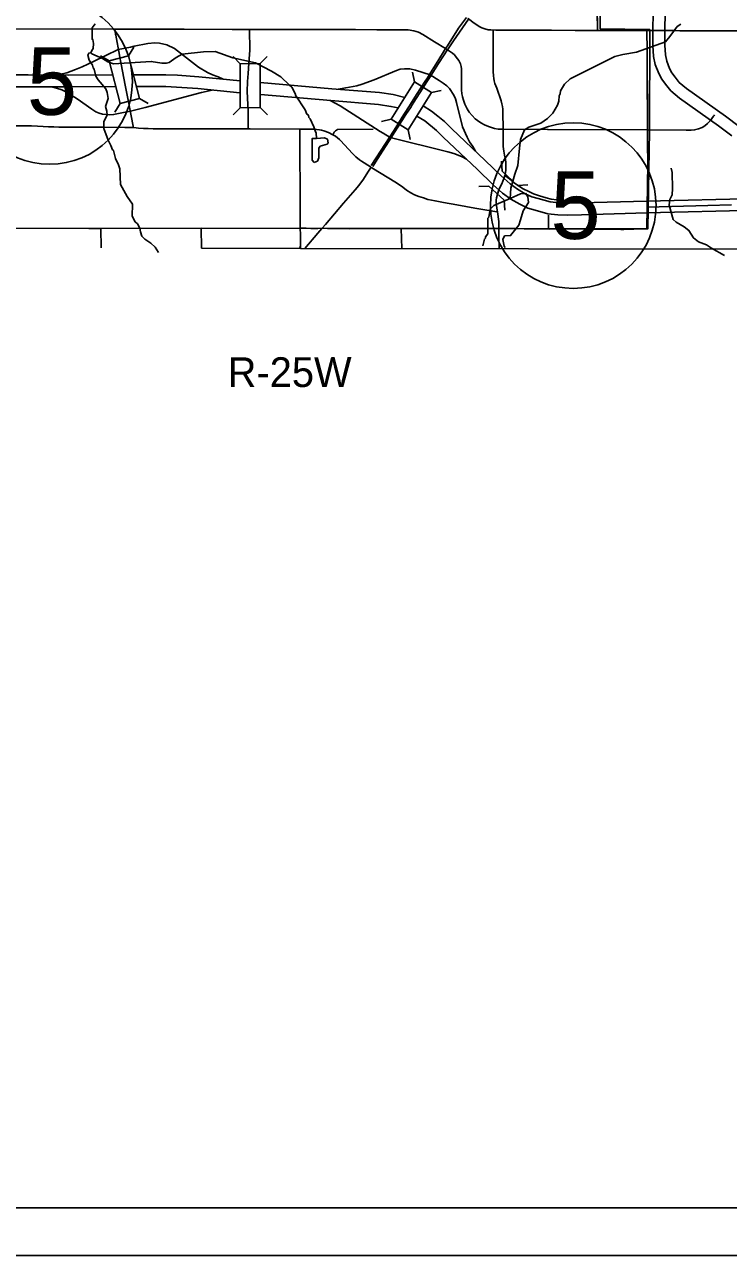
# Model space of a CAD drawing. Extents: x -1403959 to 81668, y -1400582 to 11018.
# Drawn here: x 6493 to 6836, y 7241 to 7841 of the extents above; entities that cross this region are included whole.
import ezdxf

# ---------------------------------------------------------------- set-up
doc = ezdxf.new("R2010")
doc.units = 0
for name, color, linetype in [('tdCiCityStreetTxt', 7, 'Continuous'), ('tdCiRRCL', 7, 'Continuous'), ('tdCiSectNmbr', 7, 'Continuous'), ('tdCiSectTwpRng', 7, 'Continuous'), ('tdCoCityStreetMajor', 7, 'Continuous'), ('tdCoCityStreetMinor', 7, 'Continuous'), ('tdCoClipBndry', 7, 'Continuous'), ('tdCoDivCarto', 7, 'Continuous'), ('tdCoIntCL', 7, 'Continuous'), ('tdCoSectLine', 7, 'Continuous'), ('tdCoStrucSecFHWANum', 7, 'Continuous'), ('tdCoSurfAsphalt', 7, 'Continuous'), ('tdCoSurfBitum', 7, 'Continuous'), ('tdCoSurfEarth', 7, 'Continuous')]:
    doc.layers.add(name, color=color, linetype=linetype)

msp = doc.modelspace()

# ---------------------------------------------------------------- linework, layer by layer
at = {"layer": 'tdCiCityStreetTxt'}
for p, q in [((6543.57, 7825.61), (6546.06, 7829.8)), ((6534.13, 7823.2), (6529.93, 7825.69)), ((6534.13, 7823.2), (6543.57, 7825.61)), ((6539.43, 7802.42), (6534.13, 7823.2)), ((6543.57, 7825.61), (6548.87, 7804.83)), ((6597.9, 7821.79), (6594.43, 7825.22)), ((6607.64, 7821.83), (6611.07, 7825.29)), ((6597.9, 7821.79), (6607.64, 7821.83)), ((6597.98, 7800.34), (6597.9, 7821.79)), ((6607.64, 7821.83), (6607.73, 7800.38)), ((6682.86, 7812.92), (6681.78, 7817.68)), ((6671.42, 7794.78), (6682.86, 7812.92)), ((6682.86, 7812.92), (6691.1, 7807.72)), ((6548.87, 7804.83), (6539.43, 7802.42)), ((6548.87, 7804.83), (6548.87, 7804.83)), ((6548.87, 7804.83), (6553.07, 7802.34)), ((6691.1, 7807.72), (6679.66, 7789.58)), ((6691.1, 7807.72), (6695.86, 7808.8)), ((6539.43, 7802.42), (6536.94, 7798.23)), ((6597.98, 7800.34), (6594.55, 7796.88)), ((6607.73, 7800.38), (6597.98, 7800.34)), ((6607.73, 7800.38), (6607.73, 7800.38)), ((6607.73, 7800.38), (6611.19, 7796.95)), ((6671.42, 7794.78), (6666.66, 7793.71)), ((6679.66, 7789.58), (6671.42, 7794.78)), ((6679.66, 7789.58), (6679.66, 7789.58)), ((6679.66, 7789.58), (6680.74, 7784.83))]:
    msp.add_line(p, q, dxfattribs=at)
at = {"layer": 'tdCiRRCL'}
for p, q in [((6579.15, 7731.96), (6627.37, 7731.86)), ((6627.37, 7731.86), (6997.83, 7731.15))]:
    msp.add_line(p, q, dxfattribs=at)
for points in [[(6627.37, 7731.86), (6627.23, 7738.5), (6627.19, 7741.7), (6723.95, 7741.45), (6748.03, 7741.41), (6748.63, 7741.41), (6795.97, 7741.34), (6796.1, 7751.99), (6796.35, 7773.39), (6796.26, 7789.53), (6796.11, 7824.8), (6796.13, 7828.12), (6796.01, 7837.97), (6794.48, 7837.97), (6792.7, 7837.97), (6783.45, 7837.92), (6776.54, 7837.95), (6771.85, 7837.99), (6771.78, 7850.5)], [(6771.78, 7850.5), (6771.85, 7837.99), (6776.54, 7837.95), (6783.45, 7837.92), (6792.7, 7837.97), (6794.48, 7837.97), (6796.01, 7837.97), (6796.13, 7828.12), (6796.11, 7824.8), (6796.26, 7789.53), (6796.35, 7773.39), (6796.1, 7751.99), (6825.69, 7752.71), (6837.1, 7752.99)], [(6387.68, 7731.88), (6387.75, 7734.68), (6387.88, 7736.33), (6388.19, 7738.91), (6388.51, 7740.78), (6388.71, 7741.72), (6433.9, 7741.75), (6433.91, 7756.87), (6439.59, 7756.88), (6446.88, 7752.02), (6457.28, 7751.94), (6457.24, 7741.46), (6578.95, 7741.63), (6579.15, 7731.96)], [(6837.1, 7752.99), (6825.69, 7752.71), (6796.1, 7751.99), (6795.97, 7741.34), (6748.63, 7741.41), (6748.03, 7741.41), (6723.95, 7741.45), (6627.19, 7741.7), (6627.23, 7738.5), (6627.37, 7731.86)]]:
    msp.add_lwpolyline(points, dxfattribs=at)
at = {"layer": 'tdCiSectNmbr'}
for points in [[(6708.11, 7844.34), (6704.28, 7839.09), (6698.85, 7830.41), (6697.97, 7829.14)], [(6698.84, 7828.58), (6701.73, 7832.94), (6709.07, 7843.55)], [(6708.72, 7843.9), (6709.11, 7843.61), (6711.92, 7841.54), (6714.6, 7839.79), (6715.67, 7839.26), (6717.02, 7838.72), (6718.7, 7838.36), (6719.91, 7838.25), (6722.47, 7838.19), (6726.78, 7838.11), (6734.64, 7838.13), (6749.45, 7838.05), (6761.01, 7838.02)], [(6726.04, 7789.88), (6725.9, 7798.22), (6725.83, 7799.63), (6725.66, 7800.88), (6725.38, 7802.2), (6724.94, 7803.69), (6722.82, 7809.8), (6721.99, 7812.11), (6721.61, 7813.51), (6721.39, 7814.62), (6721.23, 7815.8), (6721.12, 7817.94), (6721.11, 7829.83), (6721.14, 7838.22)], [(6761.01, 7838.02), (6762.83, 7838.02), (6762.92, 7838.02)], [(6762.92, 7838.02), (6765.9, 7837.99)], [(6765.9, 7837.99), (6766.31, 7837.99), (6771.85, 7837.99)], [(6771.85, 7837.99), (6779.66, 7837.94), (6783.45, 7837.97)], [(6783.45, 7837.97), (6787.41, 7838), (6789.83, 7838.02), (6792.7, 7838.01)], [(6792.7, 7838.01), (6794.48, 7838)], [(6794.48, 7838), (6796.01, 7838), (6796.01, 7838)], [(6796.01, 7838), (6801.6, 7837.98), (6801.97, 7837.98)], [(6801.97, 7837.98), (6802.38, 7837.98), (6804.53, 7837.95)], [(6804.53, 7837.95), (6810.13, 7837.88)], [(6810.13, 7837.88), (6811.93, 7837.86), (6815.83, 7837.84)], [(6815.83, 7837.84), (6826.23, 7837.78), (6834.06, 7837.73), (6863.52, 7837.73), (6894.38, 7837.56), (6907.58, 7837.64), (6907.8, 7837.64)], [(6697.97, 7829.14), (6697.41, 7828.3), (6694.66, 7823.77), (6690.66, 7817.42), (6689.09, 7814.92), (6688.07, 7813.33), (6683.86, 7806.72), (6680.92, 7802.14)], [(6688.84, 7812.94), (6688.84, 7812.94), (6690.45, 7815.43), (6694.5, 7821.87), (6697.21, 7826.08), (6698.37, 7827.9), (6698.69, 7828.37)], [(6698.69, 7828.37), (6698.84, 7828.58)], [(6698.84, 7828.58), (6701.26, 7826.88), (6702.22, 7826.13), (6703.17, 7824.97), (6704.38, 7823.35), (6705.15, 7821.65), (6705.47, 7820.47), (6705.68, 7819.31), (6705.73, 7817.9), (6705.73, 7815.02), (6705.62, 7811.15), (6705.68, 7809.09), (6705.91, 7807.07), (6706.11, 7805.77), (6706.13, 7805.7)], [(6543.88, 7801.67), (6541.99, 7811.39), (6539.95, 7821.58), (6539.14, 7825.73)], [(6681.71, 7801.8), (6682.51, 7803.04), (6686.53, 7809.37), (6688.84, 7812.94)], [(6706.13, 7805.7), (6706.59, 7803.99), (6707.27, 7802.16), (6707.95, 7800.78), (6708.45, 7799.83), (6709.46, 7798.18), (6710.82, 7796.51), (6712.34, 7794.9), (6713.49, 7794.08), (6715.08, 7792.96), (6716.91, 7791.97), (6718.82, 7791.14), (6721.84, 7790.25), (6723.48, 7789.98), (6725.14, 7789.86), (6726.04, 7789.83)], [(6545.96, 7790.67), (6545.86, 7791.32), (6544.09, 7800.68), (6543.88, 7801.67)], [(6680.34, 7801.22), (6677.67, 7797.05), (6673.76, 7790.7), (6672.62, 7788.95), (6666.63, 7779.75), (6661.72, 7772.18)], [(6673.25, 7788.56), (6673.31, 7788.67), (6674.74, 7790.89), (6678.64, 7796.99), (6681.11, 7800.86)], [(6680.92, 7802.14), (6680.34, 7801.22)], [(6681.11, 7800.86), (6681.71, 7801.8)], [(6815.09, 7789.38), (6817.53, 7789.41), (6819.22, 7789.56), (6821.1, 7790.09), (6822.87, 7790.78), (6824.21, 7791.55), (6825.52, 7792.7), (6826.7, 7794.01), (6828.34, 7796.16), (6828.7, 7796.64), (6828.84, 7796.86)], [(6483.25, 7791.66), (6483.38, 7791.66), (6486.25, 7791.54), (6496.24, 7791.54), (6499.15, 7791.42), (6502.05, 7791.28), (6504.58, 7791.11), (6507.11, 7790.97), (6509.64, 7790.86), (6510.86, 7790.86), (6519.03, 7790.86), (6531.05, 7790.82)], [(6531.05, 7790.82), (6531.62, 7790.82), (6541.7, 7790.74), (6545.78, 7790.67), (6545.96, 7790.67), (6546.13, 7790.67), (6548.46, 7790.47), (6550.8, 7790.31), (6553.14, 7790.2), (6555.49, 7790.12), (6557.83, 7790.09), (6560.17, 7790.09), (6562.16, 7790.11), (6562.16, 7790.11)], [(6562.16, 7790.11), (6579.82, 7790.11), (6601.89, 7790.06), (6601.91, 7790.06)], [(6601.91, 7790.06), (6602.71, 7790.05), (6626.95, 7789.94)], [(6627.19, 7741.7), (6627.06, 7763.09), (6626.98, 7775.17), (6626.95, 7789.94)], [(6626.95, 7789.94), (6630.8, 7789.92), (6633.5, 7789.91), (6635.1, 7789.77), (6636.5, 7789.57), (6637.46, 7789.44), (6638.65, 7789.13), (6640.86, 7788.26), (6643.04, 7787.21), (6644.3, 7786.44), (6646.29, 7784.85), (6646.85, 7784.37), (6648.72, 7782.34), (6650.6, 7780.18), (6652.54, 7778.07), (6654.32, 7776.45), (6656.05, 7775.05), (6656.97, 7774.33), (6661.33, 7771.58), (6661.76, 7771.31)], [(6662.5, 7771.75), (6663.8, 7773.78), (6666.09, 7777.33), (6670.48, 7784.25), (6673.25, 7788.56)], [(6723.95, 7741.45), (6723.8, 7744.88), (6723.57, 7747.14), (6723.32, 7748.62), (6722.84, 7751.41), (6722.69, 7752.93), (6722.61, 7754.42), (6722.65, 7755.38), (6722.77, 7756.41), (6723.17, 7758.18), (6723.9, 7760.42), (6724.49, 7761.78), (6725.35, 7763.35), (6726.33, 7765.96), (6726.75, 7767.28), (6727.06, 7768.64), (6727.21, 7770.08), (6727.25, 7771.51), (6727.21, 7773.6), (6727.04, 7775.21), (6726.64, 7777.18), (6726.23, 7779.21), (6726.04, 7781.51), (6725.95, 7783.93), (6726.04, 7789.83)], [(6726.04, 7789.83), (6747.63, 7789.75), (6747.82, 7789.75), (6796.26, 7789.53)], [(6796.26, 7789.53), (6815.09, 7789.38)], [(6657.92, 7765.53), (6660.16, 7768.98)], [(6660.16, 7768.98), (6661.69, 7771.35)], [(6639.48, 7743.55), (6648.29, 7753.81), (6653.99, 7760.44), (6655.72, 7762.55), (6657.92, 7765.53)], [(6722.89, 7749.65), (6723.15, 7749.61)], [(6627.19, 7741.7), (6628.56, 7741.67), (6630.07, 7741.62), (6632.27, 7741.57), (6633.94, 7741.51), (6635.69, 7741.49)], [(6627.32, 7734.17), (6627.23, 7738.5), (6627.19, 7741.7)], [(6629.41, 7731.86), (6635.74, 7739.21), (6637.69, 7741.48)], [(6637.7, 7741.49), (6637.86, 7741.68)], [(6637.86, 7741.68), (6639.48, 7743.55)], [(6640.47, 7741.47), (6642.38, 7741.45), (6650.94, 7741.43), (6663.82, 7741.48), (6677.68, 7741.48), (6685.63, 7741.54), (6700.58, 7741.5)], [(6700.58, 7741.5), (6703.37, 7741.49), (6723.05, 7741.52), (6723.95, 7741.45)], [(6724.09, 7731.68), (6723.92, 7737.9), (6723.95, 7741.45)], [(6723.95, 7741.45), (6724.81, 7741.47), (6726.78, 7741.47), (6728.47, 7741.5), (6732.89, 7741.49), (6745.95, 7741.41), (6746.72, 7741.41), (6748.03, 7741.4), (6749.98, 7741.38), (6755.95, 7741.35), (6762.37, 7741.35), (6765.2, 7741.32), (6768.54, 7741.27), (6770.28, 7741.27), (6772.9, 7741.17), (6776.56, 7741.25), (6779.39, 7741.22), (6783.36, 7741.11), (6784.8, 7741.09), (6786.13, 7741.17), (6788.42, 7741.27), (6789.68, 7741.24)], [(6626.98, 7731.87), (6627.05, 7732.06), (6627.24, 7733.44), (6627.32, 7734.17)]]:
    msp.add_lwpolyline(points, dxfattribs=at)
at = {"layer": 'tdCiSectTwpRng'}
for points in [[(6771.85, 7837.99), (6771.8, 7847.06), (6771.78, 7850.5), (6771.75, 7861.97), (6771.51, 7878.7), (6771.44, 7890.2), (6771.39, 7904.39), (6771.37, 7914.65), (6771.33, 7927.48), (6771.37, 7928.63), (6771.33, 7928.7)], [(6481.89, 7838.74), (6536.74, 7838.59), (6539.26, 7838.58), (6548.54, 7838.57), (6559.78, 7838.56)], [(6539.14, 7825.73), (6539.14, 7825.73), (6539.11, 7825.88), (6537.33, 7835.61), (6537.23, 7836.16), (6536.97, 7837.57), (6536.74, 7838.59)], [(6559.78, 7838.56), (6567.5, 7838.55), (6570.61, 7838.55)], [(6570.61, 7838.55), (6594.05, 7838.48)], [(6594.05, 7838.48), (6594.18, 7838.48), (6598.9, 7838.46)], [(6598.9, 7838.46), (6602.51, 7838.45), (6624.72, 7838.45), (6634.63, 7838.43)], [(6601.89, 7790.06), (6601.89, 7798.62), (6601.39, 7808.24), (6601.48, 7813.13), (6601.75, 7816.97), (6602.1, 7822.05), (6602.56, 7828.44), (6602.51, 7838.45)], [(6634.63, 7838.43), (6640.7, 7838.41)], [(6640.7, 7838.41), (6654.14, 7838.39), (6664.42, 7838.36), (6676.55, 7838.29), (6679.8, 7838.22), (6682.55, 7837.79), (6684.71, 7837.13), (6686.82, 7836.03), (6692.59, 7832.4), (6697.97, 7829.14), (6698.36, 7828.91), (6698.49, 7828.82)], [(6698.49, 7828.82), (6698.84, 7828.58)], [(6796.26, 7789.53), (6796.24, 7797.86), (6796.16, 7810.54)], [(6643.04, 7787.21), (6643.7, 7788.37), (6644.27, 7789.08), (6644.82, 7789.49), (6645.27, 7789.73)], [(6645.27, 7789.73), (6662.76, 7789.94)], [(6726.04, 7789.83), (6726.04, 7789.88)], [(6796.36, 7773.77), (6796.33, 7782.33), (6796.26, 7789.53)], [(6661.76, 7771.31), (6662.08, 7771.11), (6673.98, 7763.74), (6677.13, 7761.66), (6678.9, 7760.22), (6680.95, 7758.92), (6682.77, 7757.98), (6684.98, 7757.13), (6687.14, 7756.42), (6689.27, 7755.72), (6692.83, 7754.93), (6696.85, 7754.23), (6703.4, 7753.06), (6712.18, 7751.48), (6718.95, 7750.32), (6722.89, 7749.65)], [(6726.75, 7767.28), (6728.99, 7765.66), (6731.35, 7763.72), (6733.49, 7762.24), (6735.72, 7760.84), (6738.41, 7759.48), (6740.78, 7758.44), (6743.62, 7757.39), (6746.86, 7756.47), (6749.34, 7755.88), (6752.05, 7755.44), (6754.57, 7755.21), (6756.94, 7755.19), (6765.85, 7755.55), (6767.51, 7755.57)], [(6748.03, 7741.4), (6748.09, 7742.65), (6748.11, 7744.52), (6748.08, 7747.99)], [(6676.6, 7731.77), (6676.33, 7741.48)]]:
    msp.add_lwpolyline(points, dxfattribs=at)
at = {"layer": 'tdCoCityStreetMajor'}
for points in [[(6795.98, 7837.92), (6795.98, 7837.92)], [(6524.25, 7741.55), (6530.1, 7741.53)], [(6530.1, 7741.53), (6578.92, 7741.62)], [(6530.1, 7741.53), (6530.1, 7741.56)], [(6530.29, 7732.05), (6530.1, 7741.53)]]:
    msp.add_lwpolyline(points, dxfattribs=at)
at = {"layer": 'tdCoCityStreetMinor'}
msp.add_lwpolyline([(6524.25, 7741.55), (6530.1, 7741.53), (6578.92, 7741.62)], dxfattribs=at)
at = {"layer": 'tdCoClipBndry'}
msp.add_lwpolyline([(6772.45, 7982.6), (6773.16, 7838.81), (6797.35, 7838.44), (6797.21, 7788.96), (6796.4, 7741.34), (6748.6, 7741.24), (6723.92, 7741.45), (6627.16, 7741.7), (6530.1, 7741.53), (6433.87, 7741.91), (6421.98, 7741.74), (6396.34, 7741.37), (6333.72, 7741.13), (6333.65, 7836.58), (6334.16, 7936.62)], dxfattribs=at)
at = {"layer": 'tdCoDivCarto'}
for points in [[(6799.04, 7854.13), (6798.9, 7830.6), (6799.25, 7825.3), (6800.04, 7821.38), (6801.75, 7817.01), (6803.21, 7814.33), (6804.95, 7811.76), (6807.63, 7808.53), (6811.78, 7805.04), (6830.79, 7791.6), (6837.41, 7786.64)], [(6804.84, 7854.24), (6804.7, 7830.76), (6805.01, 7826.03), (6805.61, 7823.05), (6806.98, 7819.53), (6808.17, 7817.36), (6809.66, 7815.15), (6811.69, 7812.69), (6815.19, 7809.73), (6834.2, 7796.3), (6840.98, 7791.22)], [(6535.85, 7816.42), (6514.47, 7816.27), (6494.65, 7816.36), (6486.61, 7816.32)], [(6597.96, 7813.39), (6577.77, 7815.44), (6567.33, 7816.22), (6561.72, 7816.43), (6545.91, 7816.43)], [(6537.33, 7810.62), (6514.57, 7810.47), (6494.64, 7810.56), (6486.58, 7810.52)], [(6597.76, 7807.59), (6577.31, 7809.66), (6566.99, 7810.43), (6561.64, 7810.63), (6547.39, 7810.62)], [(6678.06, 7805.31), (6672.46, 7806.71), (6665.83, 7807.72), (6642.55, 7809.61), (6607.59, 7812.61)], [(6674.85, 7800.22), (6671.36, 7801.01), (6665.2, 7801.94), (6642.04, 7803.83), (6607.77, 7806.77)], [(6686.99, 7801.21), (6691.15, 7798.69), (6694.23, 7796.29), (6697.41, 7793.57), (6700.97, 7790.09), (6717.27, 7774.7), (6724.96, 7767.13), (6729.34, 7763.32), (6732.9, 7760.63), (6736.71, 7758.46), (6739.96, 7756.92), (6743.1, 7756.12), (6748.86, 7754.46), (6753.01, 7754), (6757.27, 7753.86), (6763.92, 7754), (6795.84, 7754.89), (6849.81, 7756.2)], [(6683.89, 7796.3), (6687.84, 7793.91), (6693.49, 7789.29), (6696.93, 7785.92), (6713.27, 7770.5), (6721.07, 7762.82), (6725.68, 7758.81), (6729.7, 7755.77), (6734.03, 7753.31), (6737.98, 7751.44), (6741.58, 7750.52), (6747.72, 7748.74), (6752.6, 7748.2), (6757.24, 7748.05), (6764.06, 7748.2), (6796, 7749.09), (6849.65, 7750.39)]]:
    msp.add_lwpolyline(points, dxfattribs=at)
at = {"layer": 'tdCoIntCL'}
for points in [[(6508.94, 7816.3), (6513.45, 7817.41), (6517.81, 7818.92), (6520.99, 7820.28), (6526.43, 7822.9), (6538.53, 7828.77), (6544.53, 7829.9), (6546.28, 7830.28), (6552.97, 7831.66), (6556.37, 7831.93), (6558.61, 7831.78), (6562.13, 7831), (6565.91, 7829.18), (6577.6, 7820.03), (6582.01, 7817.44), (6584.37, 7816.36), (6587.23, 7815.32), (6589.64, 7814.24)], [(6645.62, 7809.36), (6649.37, 7810.06), (6654.65, 7811.04), (6657.25, 7811.79), (6663.24, 7813.94), (6674.06, 7818.53), (6675.88, 7819.06), (6677.94, 7819.3), (6680.5, 7819.24), (6683.25, 7818.62), (6690.36, 7816.38), (6694.77, 7813.61), (6696.2, 7812.7), (6696.84, 7812.3), (6698.51, 7810.98), (6699.85, 7809.67), (6702.03, 7806.51), (6702.78, 7804.72), (6703.28, 7802.9), (6706.23, 7791.07), (6708.38, 7786), (6709.66, 7783.67), (6711.24, 7781.4), (6712.59, 7779.12)], [(6506.03, 7810.51), (6508.56, 7809.83), (6511.01, 7809), (6513.38, 7807.95), (6518.58, 7804.72), (6525.71, 7799.64), (6527.66, 7798.42), (6529.26, 7797.74), (6530.92, 7797.26), (6532.67, 7796.97), (6534.49, 7796.9), (6536.3, 7797.04), (6542.65, 7798.28), (6544.45, 7798.69), (6551.72, 7800.44), (6579.09, 7807.72), (6584.28, 7808.95)], [(6641.81, 7803.85), (6646.6, 7801.26), (6666.1, 7788.78), (6667.54, 7787.89), (6670.97, 7785.85), (6699.02, 7778.93), (6701.94, 7778.04), (6705.64, 7776.54), (6708.15, 7775.33)]]:
    msp.add_lwpolyline(points, dxfattribs=at)
at = {"layer": 'tdCoSectLine'}
for points in [[(5665.9, 10336.72), (9631.74, 10336.72), (9631.74, 7241.43), (5665.9, 7241.43)], [(5689.11, 10313.51), (9608.52, 10313.51), (9608.52, 7264.65), (5689.11, 7264.65)]]:
    msp.add_lwpolyline(points, close=True, dxfattribs=at)
at = {"layer": 'tdCoSurfAsphalt'}
for centre in [(6505.12, 7813.11), (6760.09, 7752.69)]:
    msp.add_circle(centre, 40.33, dxfattribs=at)
at = {"layer": 'tdCoSurfBitum'}
for points in [[(6558.1, 7729.82), (6556.45, 7732.51), (6554.47, 7734.35), (6551.42, 7736.34), (6550.04, 7737.87), (6549.44, 7739.86), (6549.14, 7741.69), (6547.92, 7743.83), (6546.85, 7744.75), (6545.33, 7747.5), (6545.49, 7753.45), (6542.91, 7757.13), (6539.71, 7762.93), (6539.27, 7770.57), (6538.66, 7772.56), (6537.14, 7775.61), (6536.19, 7779.59), (6535.68, 7779.9), (6534.93, 7781.89), (6533.56, 7784.49), (6531.6, 7790.15), (6531.61, 7793.66), (6533.14, 7796.71), (6533, 7798.69), (6532.4, 7800.98), (6533.63, 7804.8), (6533.18, 7807.7), (6532.58, 7809.53), (6528.78, 7813.98), (6527.71, 7815.66), (6526.81, 7819.18), (6526.35, 7819.79), (6526.05, 7821.01), (6524.38, 7823.46), (6523.78, 7825.91), (6524.24, 7826.97), (6525.16, 7827.12), (6525.62, 7828.19), (6526.39, 7829.25), (6526.55, 7831.7), (6526.25, 7833.53), (6525.79, 7833.69), (6525.81, 7839.18), (6527.34, 7841.16)], [(6812.49, 7840.96), (6810.66, 7839.9), (6807.14, 7835.02), (6804.99, 7832.43), (6790.93, 7827.42), (6784.21, 7826.21), (6780.39, 7825.3), (6758.68, 7814.36), (6755.77, 7811.77), (6753.93, 7808.57), (6753.78, 7807.04), (6753.32, 7806.13), (6753.01, 7803.53), (6752.39, 7801.55), (6750.24, 7797.73), (6747.64, 7795.14), (6744.28, 7792.86), (6738.47, 7790.89), (6736.33, 7789.52), (6734.49, 7784.94), (6733.87, 7780.67), (6733.15, 7772.28), (6731.69, 7767.97), (6729.74, 7761.23), (6729.44, 7756.06)], [(6525.16, 7827.12), (6525.61, 7826.66), (6530.95, 7824.35), (6533.54, 7822.66), (6536.3, 7821.66), (6554.65, 7822.91), (6559.84, 7821.98), (6561.98, 7821.98), (6563.35, 7822.43), (6566.72, 7824.87), (6569.62, 7826.39), (6580.01, 7827.59), (6585.81, 7827.73), (6594.36, 7824.65), (6605.35, 7822.18), (6613.13, 7818.2), (6617.71, 7815.44), (6621.98, 7811.31), (6623.05, 7810.39), (6624.87, 7806.87), (6624.87, 7806.41), (6629.59, 7799.38), (6630.35, 7797.24), (6631.11, 7796.78), (6631.42, 7795.56), (6632.02, 7794.94), (6633.85, 7791.12), (6634.61, 7788.53), (6634.91, 7788.07), (6635.06, 7785.32)], [(6635.06, 7785.32), (6632.92, 7785.32), (6632.9, 7774.79), (6633.97, 7773.72)], [(6635.06, 7785.32), (6639.03, 7785.62), (6640.41, 7785), (6640.71, 7783.32), (6640.25, 7782.56), (6636.89, 7781.65), (6636.27, 7780.73), (6636.26, 7776), (6635.5, 7774.32), (6633.97, 7773.72)], [(6833.68, 7728.38), (6827.4, 7731.9), (6824.95, 7733.59), (6821.14, 7734.97), (6818.7, 7736.96), (6816.42, 7740.63), (6814.13, 7742.32), (6810.16, 7744.62), (6808.79, 7745.84), (6806.82, 7752.87), (6807.13, 7755.62), (6808.2, 7757.91), (6808.51, 7760.96), (6808.22, 7768.75), (6807.77, 7770.88)], [(6716.11, 7733.03), (6716.88, 7736.39), (6717.34, 7736.85), (6717.34, 7737.46), (6718.56, 7738.98), (6718.58, 7746.62), (6719.04, 7747.07), (6719.66, 7750.89), (6721.49, 7752.72), (6729.44, 7756.06), (6734.49, 7758.34), (6737.08, 7758.64), (6737.99, 7756.96), (6738.29, 7754.21), (6735.69, 7750.09), (6734.46, 7745.82), (6733.54, 7743.22), (6729.56, 7738.04), (6726.65, 7737.9), (6725.89, 7736.22), (6726.49, 7732.86), (6726.95, 7732.24)]]:
    msp.add_lwpolyline(points, dxfattribs=at)
at = {"layer": 'tdCoSurfEarth'}
for p, q in [((6725.47, 7769.38), (6725.25, 7774.25)), ((6725.47, 7769.38), (6732.99, 7762.51)), ((6719.01, 7762.17), (6714.14, 7761.95)), ((6726.52, 7755.32), (6719.01, 7762.17)), ((6732.99, 7762.51), (6737.96, 7762.73)), ((6726.52, 7755.32), (6726.74, 7750.45))]:
    msp.add_line(p, q, dxfattribs=at)

# ---------------------------------------------------------------- texts
at = {"layer": 'tdCoStrucSecFHWANum'}
msp.add_text('R-25W', height=14.509, rotation=0.1011, dxfattribs=at).set_placement((6591.83, 7664.27))
at = {"layer": 'tdCoSurfAsphalt'}
for p in [(6494.02, 7796.88), (6749, 7736.46)]:
    msp.add_text('5', height=32.89, dxfattribs=at).set_placement(p)

doc.saveas('drawing.dxf')
